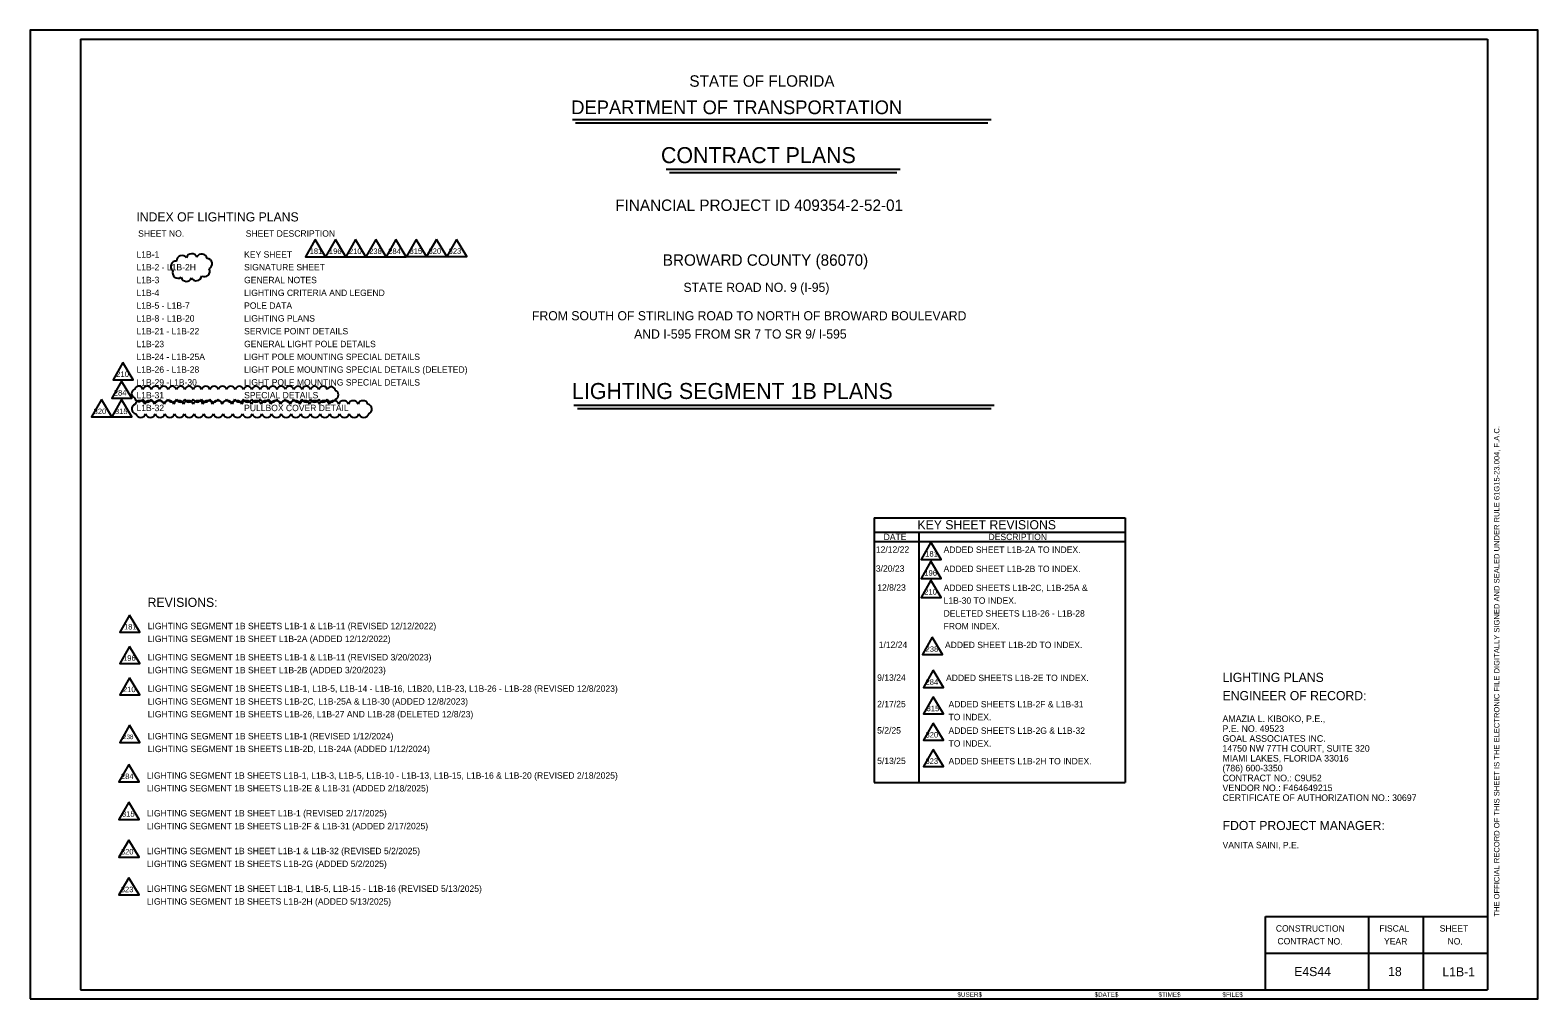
# Model space of a CAD drawing. Extents: x -818.6 to -802.1, y -2197.9 to -2175.
# Drawn here: x -818.56 to -802.06, y -2197.92 to -2187.32 of the extents above; entities that cross this region are included whole.
import ezdxf

# ---------------------------------------------------------------- set-up
doc = ezdxf.new("R2010")
doc.units = 0
for name, color, linetype in [('ActivePointCell_dp', 7, 'Continuous'), ('Cloud_dp', 7, 'Continuous'), ('PlotBorder_dp', 7, 'Continuous'), ('SheetBorder_dp', 7, 'Continuous'), ('SheetLines_dp', 7, 'Continuous'), ('SumBoxLines_dp', 7, 'Continuous'), ('TextLabel', 7, 'Continuous'), ('TextMinor', 7, 'Continuous'), ('TextMisc', 7, 'Continuous'), ('TextNotes', 7, 'Continuous'), ('TextShtNo', 7, 'Continuous'), ('TextTitle', 7, 'Continuous')]:
    doc.layers.add(name, color=color, linetype=linetype)

msp = doc.modelspace()

# ---------------------------------------------------------------- linework, layer by layer
at = {"layer": 'ActivePointCell_dp'}
msp.add_line((-802.614, -2187.419), (-802.614, -2187.419), dxfattribs=at)
at = {"layer": 'Cloud_dp'}
for points in [[(-815.443, -2189.61), (-815.551, -2189.798), (-815.33, -2189.798)], [(-815.222, -2189.61), (-815.33, -2189.798), (-815.109, -2189.798)], [(-815.002, -2189.61), (-815.109, -2189.798), (-814.889, -2189.798)], [(-814.781, -2189.61), (-814.889, -2189.798), (-814.668, -2189.798)], [(-814.56, -2189.61), (-814.667, -2189.798), (-814.447, -2189.798)], [(-814.339, -2189.609), (-814.446, -2189.797), (-814.226, -2189.797)], [(-814.118, -2189.609), (-814.226, -2189.797), (-814.005, -2189.797)], [(-813.897, -2189.609), (-814.005, -2189.797), (-813.784, -2189.797)], [(-817.548, -2190.956), (-817.656, -2191.145), (-817.435, -2191.145)], [(-817.563, -2191.159), (-817.671, -2191.347), (-817.45, -2191.347)], [(-817.783, -2191.362), (-817.891, -2191.55), (-817.671, -2191.55)], [(-817.563, -2191.362), (-817.671, -2191.55), (-817.45, -2191.55)], [(-808.706, -2192.922), (-808.814, -2193.11), (-808.593, -2193.11)], [(-808.706, -2193.13), (-808.814, -2193.318), (-808.593, -2193.318)], [(-808.706, -2193.338), (-808.814, -2193.526), (-808.593, -2193.526)], [(-817.475, -2193.719), (-817.583, -2193.907), (-817.362, -2193.907)], [(-808.691, -2193.963), (-808.799, -2194.151), (-808.578, -2194.151)], [(-817.475, -2194.062), (-817.583, -2194.25), (-817.362, -2194.25)], [(-808.68, -2194.324), (-808.787, -2194.512), (-808.567, -2194.512)], [(-817.475, -2194.405), (-817.583, -2194.593), (-817.362, -2194.593)], [(-808.68, -2194.613), (-808.787, -2194.801), (-808.567, -2194.801)], [(-817.475, -2194.924), (-817.583, -2195.113), (-817.362, -2195.113)], [(-808.68, -2194.901), (-808.787, -2195.089), (-808.567, -2195.089)], [(-808.68, -2195.19), (-808.787, -2195.378), (-808.567, -2195.378)], [(-817.485, -2195.356), (-817.593, -2195.544), (-817.372, -2195.544)], [(-817.485, -2195.768), (-817.593, -2195.957), (-817.372, -2195.957)], [(-817.485, -2196.181), (-817.593, -2196.369), (-817.372, -2196.369)], [(-817.485, -2196.594), (-817.593, -2196.782), (-817.372, -2196.782)]]:
    msp.add_lwpolyline(points, close=True, dxfattribs=at)
for centre, radius, start, end in [((-816.966, -2189.905), 0.0599, 86.9907, 231.9907), ((-816.902, -2189.845), 0.06, 35.4166, 180.4166), ((-816.795, -2189.825), 0.0599, 21.2778, 166.2778), ((-816.685, -2189.828), 0.0599, 9.9863, 154.9863), ((-816.632, -2189.877), 0.0599, 298.9542, 83.9542), ((-816.946, -2189.974), 0.0599, 159.4236, 304.4236), ((-816.854, -2190.008), 0.0599, 194.4381, 339.4381), ((-816.745, -2190.001), 0.0599, 207.5787, 352.5787), ((-816.657, -2189.957), 0.0599, 241.4449, 26.4449), ((-817.406, -2191.295), 0.0481, 107.5, 252.5), ((-817.375, -2191.264), 0.0481, 17.5, 162.5), ((-817.373, -2191.334), 0.048, 188.2189, 333.2189), ((-817.284, -2191.341), 0.0481, 197.5, 342.5), ((-817.283, -2191.264), 0.0481, 17.5, 162.5), ((-817.193, -2191.341), 0.0481, 197.5, 342.5), ((-817.192, -2191.264), 0.0481, 17.5, 162.5), ((-817.101, -2191.341), 0.0481, 197.5, 342.5), ((-817.1, -2191.264), 0.0481, 17.5, 162.5), ((-817.009, -2191.341), 0.0481, 197.5, 342.5), ((-817.008, -2191.264), 0.0481, 17.5, 162.5), ((-816.918, -2191.341), 0.0481, 197.5, 342.5), ((-816.917, -2191.264), 0.0481, 17.5, 162.5), ((-816.826, -2191.341), 0.0481, 197.5, 342.5), ((-816.825, -2191.264), 0.0481, 17.5, 162.5), ((-816.734, -2191.341), 0.0481, 197.5, 342.5), ((-816.733, -2191.264), 0.0481, 17.5, 162.5), ((-816.643, -2191.341), 0.0481, 197.5, 342.5), ((-816.642, -2191.264), 0.0481, 17.5, 162.5), ((-816.551, -2191.341), 0.0481, 197.5, 342.5), ((-816.55, -2191.264), 0.0481, 17.5, 162.5), ((-816.46, -2191.341), 0.0481, 197.5, 342.5), ((-816.458, -2191.264), 0.0481, 17.5, 162.5), ((-816.368, -2191.341), 0.0481, 197.5, 342.5), ((-816.367, -2191.264), 0.0481, 17.5, 162.5), ((-816.276, -2191.341), 0.0481, 197.5, 342.5), ((-816.275, -2191.264), 0.0481, 17.5, 162.5), ((-816.185, -2191.341), 0.0481, 197.5, 342.5), ((-816.183, -2191.264), 0.0481, 17.5, 162.5), ((-816.093, -2191.341), 0.0481, 197.5, 342.5), ((-816.092, -2191.264), 0.0481, 17.5, 162.5), ((-816.001, -2191.341), 0.0481, 197.5, 342.5), ((-816, -2191.264), 0.0481, 17.5, 162.5), ((-815.91, -2191.341), 0.0481, 197.5, 342.5), ((-815.908, -2191.264), 0.0481, 17.5, 162.5), ((-815.818, -2191.341), 0.0481, 197.5, 342.5), ((-815.817, -2191.264), 0.0481, 17.5, 162.5), ((-815.726, -2191.341), 0.0481, 197.5, 342.5), ((-815.725, -2191.264), 0.0481, 17.5, 162.5), ((-815.635, -2191.341), 0.0481, 197.5, 342.5), ((-815.633, -2191.264), 0.0481, 17.5, 162.5), ((-815.543, -2191.341), 0.0481, 197.5, 342.5), ((-815.542, -2191.264), 0.0481, 17.5, 162.5), ((-815.451, -2191.341), 0.0481, 197.5, 342.5), ((-815.45, -2191.264), 0.0481, 17.5, 162.5), ((-815.36, -2191.341), 0.0481, 197.5, 342.5), ((-815.358, -2191.264), 0.0481, 17.5, 162.5), ((-815.268, -2191.341), 0.0481, 197.5, 342.5), ((-815.27, -2191.271), 0.048, 8.2189, 153.2189), ((-815.237, -2191.31), 0.0481, 287.5, 72.5), ((-817.395, -2191.463), 0.0556, 112.2847, 257.2847), ((-817.363, -2191.429), 0.0557, 17.5, 162.5), ((-817.354, -2191.501), 0.0557, 197.5, 342.5), ((-817.257, -2191.429), 0.0557, 17.5, 162.5), ((-817.248, -2191.501), 0.0557, 197.5, 342.5), ((-817.151, -2191.429), 0.0557, 17.5, 162.5), ((-817.142, -2191.501), 0.0557, 197.5, 342.5), ((-817.045, -2191.429), 0.0557, 17.5, 162.5), ((-817.036, -2191.501), 0.0557, 197.5, 342.5), ((-816.939, -2191.429), 0.0557, 17.5, 162.5), ((-816.93, -2191.501), 0.0557, 197.5, 342.5), ((-816.832, -2191.429), 0.0557, 17.5, 162.5), ((-816.823, -2191.501), 0.0557, 197.5, 342.5), ((-816.726, -2191.429), 0.0557, 17.5, 162.5), ((-816.717, -2191.501), 0.0557, 197.5, 342.5), ((-816.62, -2191.429), 0.0557, 17.5, 162.5), ((-816.611, -2191.501), 0.0557, 197.5, 342.5), ((-816.514, -2191.429), 0.0557, 17.5, 162.5), ((-816.505, -2191.501), 0.0557, 197.5, 342.5), ((-816.408, -2191.429), 0.0557, 17.5, 162.5), ((-816.399, -2191.501), 0.0557, 197.5, 342.5), ((-816.301, -2191.429), 0.0557, 17.5, 162.5), ((-816.293, -2191.501), 0.0557, 197.5, 342.5), ((-816.195, -2191.429), 0.0557, 17.5, 162.5), ((-816.186, -2191.501), 0.0557, 197.5, 342.5), ((-816.089, -2191.429), 0.0557, 17.5, 162.5), ((-816.08, -2191.501), 0.0557, 197.5, 342.5), ((-815.983, -2191.429), 0.0557, 17.5, 162.5), ((-815.974, -2191.501), 0.0557, 197.5, 342.5), ((-815.877, -2191.429), 0.0557, 17.5, 162.5), ((-815.868, -2191.501), 0.0557, 197.5, 342.5), ((-815.77, -2191.429), 0.0557, 17.5, 162.5), ((-815.762, -2191.501), 0.0557, 197.5, 342.5), ((-815.664, -2191.429), 0.0557, 17.5, 162.5), ((-815.655, -2191.501), 0.0557, 197.5, 342.5), ((-815.558, -2191.429), 0.0557, 17.5, 162.5), ((-815.549, -2191.501), 0.0557, 197.5, 342.5), ((-815.452, -2191.429), 0.0557, 17.5, 162.5), ((-815.443, -2191.501), 0.0557, 197.5, 342.5), ((-815.346, -2191.429), 0.0557, 17.5, 162.5), ((-815.337, -2191.501), 0.0557, 197.5, 342.5), ((-815.239, -2191.429), 0.0557, 17.5, 162.5), ((-815.231, -2191.501), 0.0557, 197.5, 342.5), ((-815.133, -2191.429), 0.0557, 17.5, 162.5), ((-815.124, -2191.501), 0.0557, 197.5, 342.5), ((-815.027, -2191.429), 0.0557, 17.5, 162.5), ((-815.018, -2191.501), 0.0557, 197.5, 342.5), ((-814.921, -2191.429), 0.0557, 17.5, 162.5), ((-814.912, -2191.501), 0.0557, 197.5, 342.5), ((-814.88, -2191.466), 0.0556, 292.2847, 77.2847)]:
    msp.add_arc(centre, radius, start, end, dxfattribs=at)
at = {"layer": 'PlotBorder_dp'}
msp.add_lwpolyline([(-818.564, -2197.919), (-802.064, -2197.919), (-802.064, -2187.319), (-818.564, -2187.319)], close=True, dxfattribs=at)
at = {"layer": 'SheetBorder_dp'}
for p, q in [((-818.014, -2187.419), (-818.014, -2197.819)), ((-818.014, -2187.419), (-802.614, -2187.419)), ((-802.614, -2187.419), (-802.614, -2197.819)), ((-818.014, -2197.819), (-802.614, -2197.819))]:
    msp.add_line(p, q, dxfattribs=at)
at = {"layer": 'SheetLines_dp'}
for p, q in [((-805.044, -2197.019), (-802.614, -2197.019)), ((-805.044, -2197.819), (-805.044, -2197.019)), ((-803.914, -2197.819), (-803.914, -2197.019)), ((-803.314, -2197.819), (-803.314, -2197.019)), ((-805.044, -2197.419), (-802.614, -2197.419))]:
    msp.add_line(p, q, dxfattribs=at)
at = {"layer": 'SumBoxLines_dp'}
for p, q in [((-809.327, -2192.654), (-809.327, -2195.552)), ((-809.327, -2192.654), (-806.58, -2192.654)), ((-806.58, -2192.654), (-806.58, -2195.552)), ((-809.327, -2192.814), (-806.58, -2192.814)), ((-808.837, -2192.814), (-808.837, -2195.552)), ((-809.327, -2192.914), (-806.58, -2192.914)), ((-809.327, -2195.552), (-806.58, -2195.552))]:
    msp.add_line(p, q, dxfattribs=at)
at = {"layer": 'TextTitle'}
for p, q in [((-812.63, -2188.295), (-808.048, -2188.295)), ((-812.597, -2188.333), (-808.083, -2188.333)), ((-811.605, -2188.84), (-809.044, -2188.84)), ((-811.566, -2188.878), (-809.077, -2188.878)), ((-812.614, -2191.421), (-808.015, -2191.421)), ((-812.575, -2191.459), (-808.047, -2191.459))]:
    msp.add_line(p, q, dxfattribs=at)

# ---------------------------------------------------------------- texts
at = {"layer": 'Cloud_dp'}
for s, height, p in [('181', 0.06, (-815.505, -2189.768)), ('196', 0.06, (-815.294, -2189.768)), ('210', 0.06, (-815.075, -2189.768)), ('238', 0.06, (-814.854, -2189.768)), ('284', 0.06, (-814.645, -2189.768)), ('315', 0.06, (-814.412, -2189.767)), ('320', 0.06, (-814.204, -2189.767)), ('323', 0.06, (-813.984, -2189.767)), ('210', 0.06, (-817.621, -2191.114)), ('284', 0.06, (-817.648, -2191.317)), ('320', 0.06, (-817.869, -2191.52)), ('315', 0.06, (-817.636, -2191.52)), ('181', 0.06, (-808.768, -2193.079)), ('196', 0.06, (-808.778, -2193.288)), ('210', 0.06, (-808.779, -2193.496)), ('181', 0.06, (-817.537, -2193.877)), ('196', 0.06, (-817.547, -2194.22)), ('238', 0.06, (-808.764, -2194.121)), ('284', 0.06, (-808.765, -2194.482)), ('210', 0.06, (-817.548, -2194.563)), ('315', 0.06, (-808.753, -2194.771)), ('238', 0.05, (-817.548, -2195.077)), ('320', 0.06, (-808.765, -2195.059)), ('323', 0.06, (-808.766, -2195.348)), ('284', 0.06, (-817.57, -2195.514)), ('315', 0.06, (-817.559, -2195.926)), ('320', 0.06, (-817.571, -2196.339)), ('323', 0.06, (-817.572, -2196.752))]:
    msp.add_text(s, height=height, rotation=0, dxfattribs=at).set_placement(p)
at = {"layer": 'TextLabel'}
for s, height, p in [('FINANCIAL PROJECT ID 409354-2-52-01', 0.125, (-812.16, -2189.297)), ('INDEX OF LIGHTING PLANS', 0.1, (-817.401, -2189.412)), ('L1B-1', 0.07, (-817.4, -2189.808)), ('L1B-2 - L1B-2H', 0.07, (-817.4, -2189.948)), ('SIGNATURE SHEET', 0.07, (-816.222, -2189.948)), ('KEY SHEET', 0.07, (-816.222, -2189.808)), ('BROWARD COUNTY (86070)', 0.125, (-811.64, -2189.897)), ('L1B-3', 0.07, (-817.4, -2190.088)), ('GENERAL NOTES', 0.07, (-816.222, -2190.088)), ('L1B-4', 0.07, (-817.4, -2190.228)), ('LIGHTING CRITERIA AND LEGEND', 0.07, (-816.222, -2190.228)), ('STATE ROAD NO. 9 (I-95)', 0.1, (-811.414, -2190.183)), ('L1B-5 - L1B-7', 0.07, (-817.4, -2190.368)), ('POLE DATA', 0.07, (-816.222, -2190.368)), ('L1B-8 - L1B-20', 0.07, (-817.4, -2190.508)), ('LIGHTING PLANS', 0.07, (-816.222, -2190.508)), ('FROM SOUTH OF STIRLING ROAD TO NORTH OF BROWARD BOULEVARD', 0.1, (-813.072, -2190.494)), ('L1B-21 - L1B-22', 0.07, (-817.4, -2190.648)), ('SERVICE POINT DETAILS', 0.07, (-816.222, -2190.648)), ('AND I-595 FROM SR 7 TO SR 9/ I-595', 0.1, (-811.954, -2190.694)), ('L1B-23', 0.07, (-817.4, -2190.788)), ('L1B-24 - L1B-25A', 0.07, (-817.4, -2190.928)), ('GENERAL LIGHT POLE DETAILS', 0.07, (-816.222, -2190.788)), ('LIGHT POLE MOUNTING SPECIAL DETAILS', 0.07, (-816.222, -2190.928)), ('L1B-26 - L1B-28', 0.07, (-817.4, -2191.068)), ('LIGHT POLE MOUNTING SPECIAL DETAILS (DELETED)', 0.07, (-816.222, -2191.068)), ('L1B-29 -L1B-30', 0.07, (-817.4, -2191.208)), ('LIGHT POLE MOUNTING SPECIAL DETAILS', 0.07, (-816.222, -2191.208)), ('L1B-31', 0.07, (-817.4, -2191.348)), ('SPECIAL DETAILS', 0.07, (-816.222, -2191.348)), ('L1B-32', 0.07, (-817.4, -2191.488)), ('PULLBOX COVER DETAIL', 0.07, (-816.222, -2191.488)), ('KEY SHEET REVISIONS', 0.1, (-808.853, -2192.781)), ('REVISIONS:', 0.1, (-817.278, -2193.63)), ('LIGHTING PLANS', 0.1, (-805.514, -2194.451)), ('ENGINEER OF RECORD:', 0.1, (-805.514, -2194.651)), ('AMAZIA L. KIBOKO, P.E.,', 0.07202, (-805.515, -2194.89)), ('P.E. NO. 49523', 0.07202, (-805.515, -2194.998)), ('GOAL ASSOCIATES INC. ', 0.07202, (-805.515, -2195.106)), ('14750 NW 77TH COURT, SUITE 320', 0.07202, (-805.515, -2195.214)), ('MIAMI LAKES, FLORIDA 33016', 0.07202, (-805.515, -2195.322)), ('CONTRACT NO.: C9U52', 0.07202, (-805.515, -2195.538)), ('(786) 600-3350', 0.07202, (-805.515, -2195.43)), ('VENDOR NO.: F464649215', 0.07202, (-805.515, -2195.646)), ('CERTIFICATE OF AUTHORIZATION NO.: 30697', 0.07202, (-805.515, -2195.754)), ('E4S44', 0.1, (-804.73, -2197.67)), ('18', 0.1, (-803.702, -2197.67))]:
    msp.add_text(s, height=height, dxfattribs=at).set_placement(p)
at = {"layer": 'TextMinor'}
for s, height, p in [('12/12/22', 0.07, (-809.308, -2193.037)), ('ADDED SHEET L1B-2A TO INDEX.', 0.07, (-808.567, -2193.039)), ('3/20/23', 0.07, (-809.308, -2193.245)), ('ADDED SHEET L1B-2B TO INDEX.', 0.07, (-808.567, -2193.248)), ('12/8/23', 0.07, (-809.293, -2193.453)), ('ADDED SHEETS L1B-2C, L1B-25A & ', 0.07, (-808.567, -2193.456)), ('L1B-30 TO INDEX.', 0.07, (-808.567, -2193.596)), ('DELETED SHEETS L1B-26 - L1B-28 ', 0.07, (-808.567, -2193.736)), ('FROM INDEX.', 0.07, (-808.567, -2193.876)), ('1/12/24', 0.07, (-809.277, -2194.079)), ('ADDED SHEET L1B-2D TO INDEX.', 0.07, (-808.552, -2194.081)), ('9/13/24', 0.07, (-809.294, -2194.439)), ('ADDED SHEETS L1B-2E TO INDEX.', 0.07, (-808.54, -2194.442)), ('2/17/25', 0.07, (-809.294, -2194.728)), ('ADDED SHEETS L1B-2F & L1B-31      ', 0.07, (-808.513, -2194.73)), ('TO INDEX.', 0.07, (-808.513, -2194.87)), ('5/2/25', 0.07, (-809.294, -2195.016)), ('ADDED SHEETS L1B-2G & L1B-32      ', 0.07, (-808.513, -2195.019)), ('TO INDEX.', 0.07, (-808.513, -2195.159)), ('5/13/25', 0.07, (-809.294, -2195.35)), ('ADDED SHEETS L1B-2H TO INDEX.', 0.07, (-808.513, -2195.353)), ('$USER$', 0.05, (-808.415, -2197.897))]:
    msp.add_text(s, height=height, dxfattribs=at).set_placement(p)
for s, p in [('$DATE$', (-806.915, -2197.897)), ('$TIME$', (-806.215, -2197.897)), ('$FILE$', (-805.515, -2197.897))]:
    msp.add_text(s, height=0.05, rotation=360, dxfattribs=at).set_placement(p)
at = {"layer": 'TextMisc'}
msp.add_text('THE OFFICIAL RECORD OF THIS SHEET IS THE ELECTRONIC FILE DIGITALLY SIGNED AND SEALED UNDER RULE 61G15-23.004, F.A.C.', height=0.06, rotation=90, dxfattribs=at).set_placement((-802.484, -2197.019))
at = {"layer": 'TextNotes'}
for s, height, p in [('SHEET NO.', 0.07, (-817.382, -2189.579)), ('SHEET DESCRIPTION', 0.07, (-816.204, -2189.579)), ('DATE', 0.07, (-809.223, -2192.899)), ('DESCRIPTION', 0.07, (-808.075, -2192.899)), ('LIGHTING SEGMENT 1B SHEETS L1B-1 & L1B-11 (REVISED 12/12/2022)', 0.06998, (-817.277, -2193.874)), ('LIGHTING SEGMENT 1B SHEET L1B-2A (ADDED 12/12/2022)', 0.06998, (-817.277, -2194.014)), ('LIGHTING SEGMENT 1B SHEETS L1B-1 & L1B-11 (REVISED 3/20/2023)', 0.06998, (-817.277, -2194.216)), ('LIGHTING SEGMENT 1B SHEET L1B-2B (ADDED 3/20/2023)', 0.06998, (-817.277, -2194.356)), ('LIGHTING SEGMENT 1B SHEETS L1B-1, L1B-5, L1B-14 - L1B-16, L1B20, L1B-23, L1B-26 - L1B-28 (REVISED 12/8/2023)', 0.069982, (-817.277, -2194.559)), ('LIGHTING SEGMENT 1B SHEETS L1B-2C, L1B-25A & L1B-30 (ADDED 12/8/2023)', 0.06998, (-817.277, -2194.699)), ('LIGHTING SEGMENT 1B SHEETS L1B-26, L1B-27 AND L1B-28 (DELETED 12/8/23)', 0.06998, (-817.277, -2194.839)), ('LIGHTING SEGMENT 1B SHEETS L1B-1 (REVISED 1/12/2024)', 0.06998, (-817.277, -2195.079)), ('LIGHTING SEGMENT 1B SHEETS L1B-2D, L1B-24A (ADDED 1/12/2024)', 0.06998, (-817.277, -2195.219)), ('LIGHTING SEGMENT 1B SHEETS L1B-1, L1B-3, L1B-5, L1B-10 - L1B-13, L1B-15, L1B-16 & L1B-20 (REVISED 2/18/2025)', 0.069982, (-817.287, -2195.51)), ('LIGHTING SEGMENT 1B SHEETS L1B-2E & L1B-31 (ADDED 2/18/2025)', 0.06998, (-817.287, -2195.65)), ('LIGHTING SEGMENT 1B SHEET L1B-1 (REVISED 2/17/2025)', 0.06998, (-817.287, -2195.923)), ('FDOT PROJECT MANAGER:', 0.1, (-805.514, -2196.072)), ('LIGHTING SEGMENT 1B SHEETS L1B-2F & L1B-31 (ADDED 2/17/2025)', 0.06998, (-817.287, -2196.063)), ('LIGHTING SEGMENT 1B SHEET L1B-1 & L1B-32 (REVISED 5/2/2025)', 0.06998, (-817.287, -2196.336)), ('VANITA SAINI, P.E.', 0.07, (-805.514, -2196.271)), ('LIGHTING SEGMENT 1B SHEETS L1B-2G (ADDED 5/2/2025)', 0.06998, (-817.287, -2196.476)), ('LIGHTING SEGMENT 1B SHEET L1B-1, L1B-5, L1B-15 - L1B-16 (REVISED 5/13/2025)', 0.06998, (-817.287, -2196.748)), ('LIGHTING SEGMENT 1B SHEETS L1B-2H (ADDED 5/13/2025)', 0.06998, (-817.287, -2196.888))]:
    msp.add_text(s, height=height, dxfattribs=at).set_placement(p)
for s, p in [('CONSTRUCTION', (-804.931, -2197.183)), ('FISCAL', (-803.798, -2197.183)), ('SHEET', (-803.138, -2197.183)), ('CONTRACT NO.', (-804.913, -2197.323)), ('YEAR', (-803.747, -2197.324)), ('NO.', (-803.052, -2197.324))]:
    msp.add_text(s, height=0.07, rotation=359.8607, dxfattribs=at).set_placement(p)
at = {"layer": 'TextShtNo'}
msp.add_text('L1B-1', height=0.1, dxfattribs=at).set_placement((-803.108, -2197.673))
at = {"layer": 'TextTitle'}
for s, height, p in [('STATE OF FLORIDA', 0.125, (-811.349, -2187.938)), ('DEPARTMENT OF TRANSPORTATION', 0.15, (-812.642, -2188.238)), ('CONTRACT PLANS', 0.175, (-811.66, -2188.774)), ('LIGHTING SEGMENT 1B PLANS', 0.175, (-812.634, -2191.355))]:
    msp.add_text(s, height=height, dxfattribs=at).set_placement(p)

doc.saveas('drawing.dxf')
